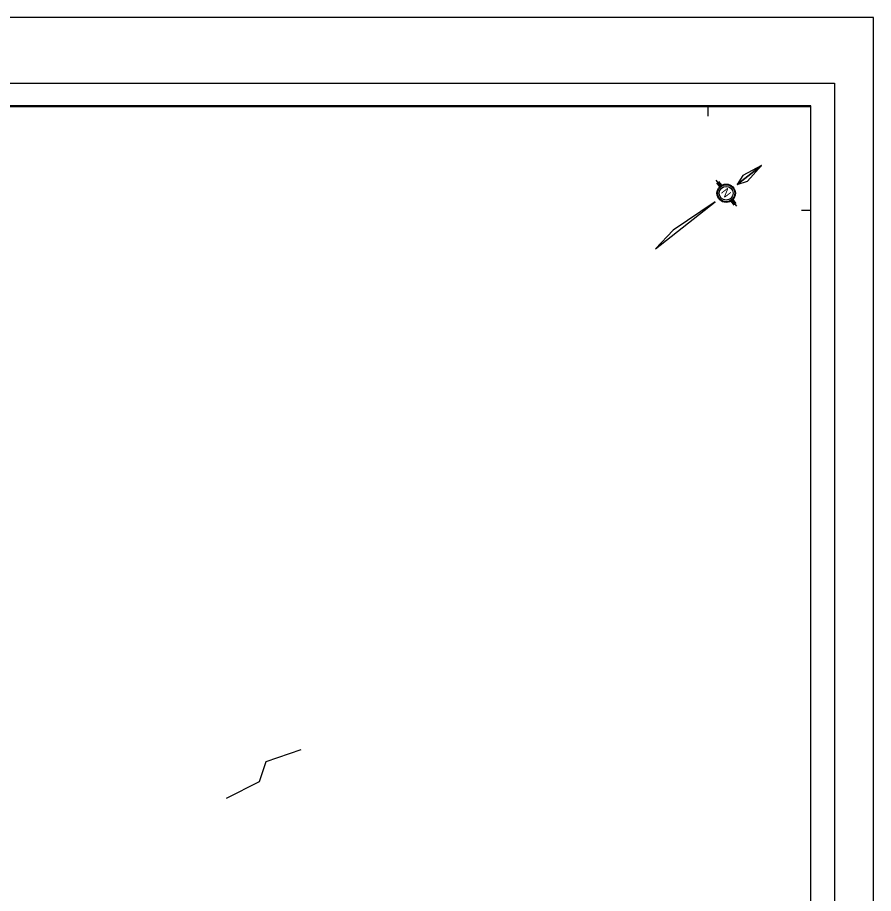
# Model space of a CAD drawing. Extents: x 602909 to 603631, y 4846273 to 4846729.
# Drawn here: x 603194.8 to 603377, y 4846459.2 to 4846645.6 of the extents above; entities that cross this region are included whole.
import ezdxf

# ---------------------------------------------------------------- set-up
doc = ezdxf.new("R2010")
doc.units = 0
for name, color, linetype in [('-PRINT FULLSIZE', 7, 'Continuous'), ('-PRINT HALFSIZE', 7, 'Continuous'), ('ENG_BORDER', 7, 'Continuous'), ('ENG_TITLEBLOCK', 7, 'Continuous'), ('SL - New Duct - OH SL', 7, 'Continuous'), ('SL - Roadway Text', 7, 'Continuous')]:
    doc.layers.add(name, color=color, linetype=linetype)

msp = doc.modelspace()

# ---------------------------------------------------------------- linework, layer by layer
at = {"layer": '-PRINT FULLSIZE'}
msp.add_lwpolyline([(602930, 4846340.65), (603377.03, 4846340.65), (603377.03, 4846645.65), (602930, 4846645.65)], close=True, dxfattribs=at)
at = {"layer": '-PRINT HALFSIZE'}
msp.add_lwpolyline([(602959.8, 4846631.64), (603368.72, 4846631.64), (603368.72, 4846352.64), (602959.8, 4846352.64)], close=True, dxfattribs=at)
at = {"layer": 'ENG_BORDER'}
for p, q in [((603363.72, 4846626.85), (602977.52, 4846626.85)), ((603363.72, 4846357.64), (603363.72, 4846626.85))]:
    msp.add_line(p, q, dxfattribs=at)
msp.add_lwpolyline([(602977.52, 4846357.64), (603363.72, 4846357.64), (603363.72, 4846626.64), (602977.52, 4846626.64)], close=True, dxfattribs=at)
at = {"layer": 'ENG_TITLEBLOCK'}
for p, q in [((603341.72, 4846626.64), (603341.72, 4846624.64)), ((603361.72, 4846604.64), (603363.72, 4846604.64))]:
    msp.add_line(p, q, dxfattribs=at)
at = {"layer": 'SL - New Duct - OH SL'}
msp.add_lwpolyline([(603239.26, 4846479.48), (603246.26, 4846483.02), (603247.71, 4846487.32), (603255.13, 4846489.88)], dxfattribs=at)
msp.add_lwpolyline([(603239.26, 4846479.48), (603246.26, 4846483.02), (603247.71, 4846487.32), (603255.13, 4846489.88)], dxfattribs=at)
msp.add_lwpolyline([(603239.26, 4846479.48), (603246.26, 4846483.02), (603247.71, 4846487.32), (603255.13, 4846489.88)], dxfattribs=at)
at = {"layer": 'SL - Roadway Text'}
for p, q in [((603343.49, 4846611.02), (603344.46, 4846609.79)), ((603343.61, 4846610.44), (603344.26, 4846609.61)), ((603344.02, 4846610.76), (603344.67, 4846609.94)), ((603346.66, 4846606.57), (603347.3, 4846605.74)), ((603346.87, 4846606.71), (603347.84, 4846605.48)), ((603347.07, 4846606.89), (603347.71, 4846606.07))]:
    msp.add_line(p, q, dxfattribs=at)
for points in [[(603353.18, 4846614.16), (603349.23, 4846612.05), (603347.99, 4846610.08)], [(603353.18, 4846614.16), (603347.99, 4846610.08), (603350.2, 4846610.82)], [(603343.34, 4846606.43), (603334.39, 4846600.38), (603330.63, 4846596.44)]]:
    msp.add_lwpolyline(points, close=True, dxfattribs=at)
for radius in [1.96, 1.81, 1.46]:
    msp.add_circle((603345.66, 4846608.25), radius, dxfattribs=at)

# ---------------------------------------------------------------- texts
msp.add_text('N', height=1.73, rotation=308.1708, dxfattribs=at).set_placement((603344.45, 4846608.46))

doc.saveas('drawing.dxf')
